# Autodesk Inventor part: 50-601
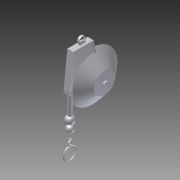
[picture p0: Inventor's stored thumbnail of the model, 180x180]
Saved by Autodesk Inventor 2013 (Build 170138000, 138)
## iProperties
Created: 2004-11
Part Number: 50-601
Document SubType Name: Modeling
Designer: Autodesk, Inc.
Manufacturer: Standard
Standards Organization: Custom
Catalog Web Link: http://www.parker.com/ead/cm1.asp?cmid=809
Vendor: PARKER IPS
Mass: 622.981 g
Surface Area: 555.93 cm^2
Volume: 622.981 cm^3
Density: 1 g/cm^3
Description: Tool Balancer,  Zero Gravity, 2.6~5.7 LBS
Material: Allgemein
CAGE: 1LJX3
Dept. ID: Product Design
Description #2: ---
Finish #1: ---
Finish #2: ---
Material ID: ---
Project Number: ---
Description: "Zero Gravity" Tool Balancer
Order Number: 50-600
Selection: "Zero Gravity" Tool Balancer
Supplier: Parker Hannifin Corp., Industrial Profile Systems Div.
Author: Autodesk, Inc.
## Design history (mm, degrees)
derived "50-60x Zero Gravity Tool Balancer.ipt"
body "Solid1"
tag "TaggingFeature2"
workaxis "Work Axis3"
workaxis "Work Axis5"
feature "Solid1::50-60x Zero Gravity Tool Balancer.ipt"
other parameters: "d1" = 0, "d2" = 0
